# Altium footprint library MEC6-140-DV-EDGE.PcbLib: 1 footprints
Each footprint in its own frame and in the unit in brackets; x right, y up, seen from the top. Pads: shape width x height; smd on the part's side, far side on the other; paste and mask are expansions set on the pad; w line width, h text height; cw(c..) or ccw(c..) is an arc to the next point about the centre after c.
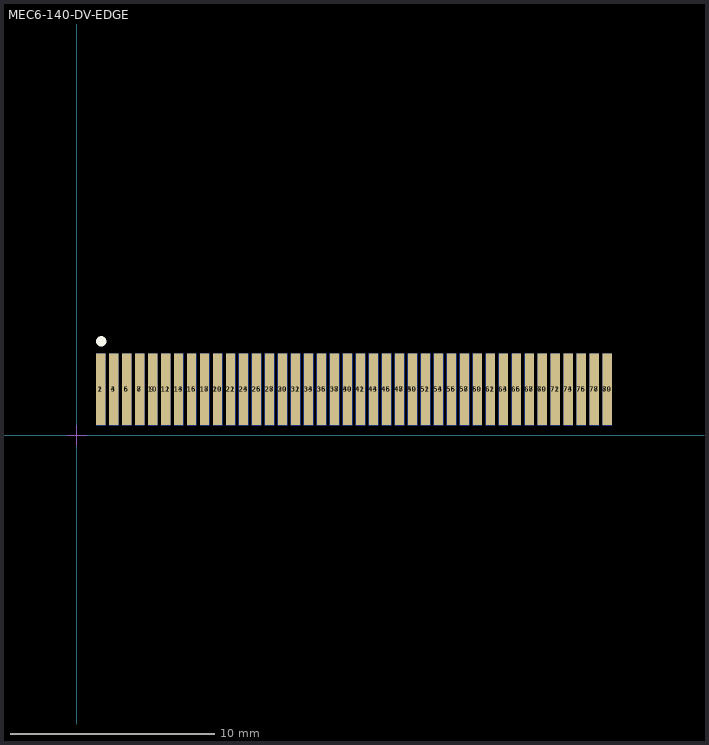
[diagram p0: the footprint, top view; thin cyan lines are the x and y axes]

## MEC6-140-DV-EDGE [mm] "0.635mm pitch, 80 pin, mini edge card"
height 8.65
pads (80):
  rect 0.45x3.5 smd: 1(1.172,2.25) 3(1.807,2.25) 5(2.442,2.25) 7(3.077,2.25) 9(3.712,2.25) 11(4.347,2.25) 13(4.982,2.25) 15(5.617,2.25) 17(6.252,2.25) 19(6.887,2.25) 21(7.522,2.25) 23(8.157,2.25) 25(8.792,2.25) 27(9.427,2.25) 29(10.062,2.25) 31(10.697,2.25) 33(11.332,2.25) 35(11.967,2.25) 37(12.602,2.25) 39(13.237,2.25) 41(13.872,2.25) 43(14.507,2.25) 45(15.142,2.25) 47(15.777,2.25) 49(16.412,2.25) 51(17.047,2.25) 53(17.682,2.25) 55(18.317,2.25) 57(18.952,2.25) 59(19.587,2.25) 61(20.222,2.25) 63(20.857,2.25) 65(21.492,2.25) 67(22.127,2.25) 69(22.762,2.25) 71(23.397,2.25) 73(24.032,2.25) 75(24.667,2.25) 77(25.302,2.25) 79(25.937,2.25)
  rect 0.45x3.5 smd far side: 2(1.172,2.25) 4(1.807,2.25) 6(2.442,2.25) 8(3.077,2.25) 10(3.712,2.25) 12(4.347,2.25) 14(4.982,2.25) 16(5.617,2.25) 18(6.252,2.25) 20(6.887,2.25) 22(7.522,2.25) 24(8.157,2.25) 26(8.792,2.25) 28(9.427,2.25) 30(10.062,2.25) 32(10.697,2.25) 34(11.332,2.25) 36(11.967,2.25) 38(12.602,2.25) 40(13.237,2.25) 42(13.872,2.25) 44(14.507,2.25) 46(15.142,2.25) 48(15.777,2.25) 50(16.412,2.25) 52(17.047,2.25) 54(17.682,2.25) 56(18.317,2.25) 58(18.952,2.25) 60(19.587,2.25) 62(20.222,2.25) 64(20.857,2.25) 66(21.492,2.25) 68(22.127,2.25) 70(22.762,2.25) 72(23.397,2.25) 74(24.032,2.25) 76(24.667,2.25) 78(25.302,2.25) 80(25.937,2.25)
Top Overlay:
  circle w0.25: c1.2,4.6 r0.125
Top Solder:
  region: -0.05,4.1 27.15,4.1 27.15,-0.05 -0.05,-0.05
Bottom Solder:
  region: -0.05,4.1 27.15,4.1 27.15,-0.05 -0.05,-0.05
Mechanical 13:
  text ".Designator" at 0.254,0.254 h1.52
Mechanical 15:
  lines w0.05: -0.5,0 0.5,0 ; 0,-0.5 0,0.5
Drill Drawing:
  lines w0.025: -2,6.5 -0.8,6.5 cw(c-0.8,5.7) 0,5.7 0,0 27.11,0 27.11,5.7 cw(c27.91,5.7) 27.91,6.5 29.11,6.5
